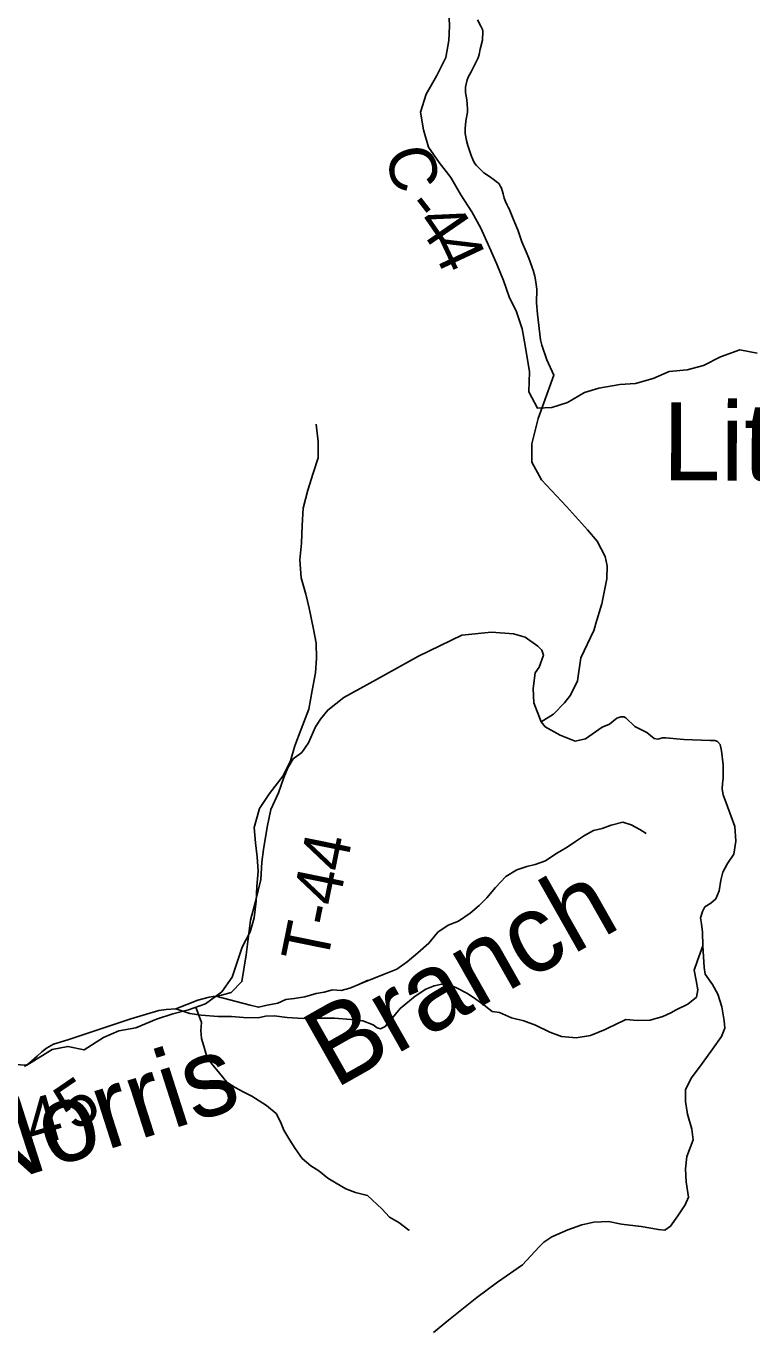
# Model space of a CAD drawing. Extents: x 0 to 34, y 0 to 22.
# Drawn here: x 5.252 to 6.132, y 18.512 to 20.093 of the extents above; entities that cross this region are included whole.
import ezdxf

# ---------------------------------------------------------------- set-up
doc = ezdxf.new("R2010")
doc.units = 0
for name, color, linetype in [('GM_X_County_Road', 7, 'Continuous'), ('GM_X_County_Road_Text', 7, 'Continuous'), ('GM_X_Minor_River', 7, 'Continuous'), ('GM_X_Minor_River_Text', 7, 'Continuous'), ('GM_X_Township_Road', 7, 'Continuous'), ('GM_X_Township_Road_Text', 7, 'Continuous')]:
    doc.layers.add(name, color=color, linetype=linetype)

msp = doc.modelspace()

# ---------------------------------------------------------------- linework, layer by layer
at = {"layer": 'GM_X_County_Road'}
for points in [[(5.8698, 19.7849), (5.8688, 19.7894), (5.8668, 19.7965), (5.8659, 19.7997), (5.8634, 19.8067), (5.8618, 19.8111), (5.8584, 19.8189), (5.8531, 19.8311), (5.8486, 19.8442), (5.842, 19.8611), (5.8378, 19.8711), (5.8368, 19.8733), (5.8355, 19.8754), (5.8335, 19.8799), (5.8318, 19.8841), (5.8304, 19.8895), (5.8284, 19.8961), (5.8272, 19.8984), (5.8263, 19.9005), (5.8249, 19.9021), (5.8221, 19.9042), (5.8186, 19.9072), (5.8129, 19.911), (5.807, 19.9148), (5.8013, 19.9205), (5.7981, 19.9236), (5.7958, 19.9267), (5.7936, 19.9309), (5.7916, 19.9357), (5.7901, 19.9406), (5.7877, 19.948), (5.7861, 19.9541), (5.7843, 19.9626), (5.7843, 19.9686), (5.7852, 19.9774), (5.7873, 19.9885), (5.7871, 19.9921), (5.787, 19.9988), (5.7863, 20.0033), (5.7848, 20.0124), (5.7848, 20.0187), (5.7856, 20.0226), (5.787, 20.0279), (5.7885, 20.032), (5.7916, 20.0374), (5.8004, 20.0543), (5.8015, 20.0584), (5.8028, 20.0651), (5.8056, 20.0761), (5.8057, 20.0868), (5.8053, 20.0889), (5.8048, 20.0905), (5.8033, 20.093), (5.7996, 20.1007)], [(5.9427, 19.3663), (5.9504, 19.3912), (5.9562, 19.4218), (5.9568, 19.4375), (5.9545, 19.449), (5.9445, 19.4675), (5.9329, 19.4813), (5.9076, 19.5097), (5.8769, 19.542), (5.8653, 19.5635), (5.8653, 19.5858), (5.873, 19.6166), (5.8922, 19.6692), (5.8834, 19.6876), (5.8773, 19.7057), (5.876, 19.7119), (5.8723, 19.743), (5.871, 19.7568), (5.8713, 19.7736), (5.8698, 19.7849)], [(5.8768, 19.2482), (5.8917, 19.2573), (5.9049, 19.2713), (5.9124, 19.2804), (5.9206, 19.2978), (5.9248, 19.3259), (5.9405, 19.359), (5.9422, 19.3644), (5.9427, 19.3663)], [(5.9738, 18.8837), (5.9793, 18.8865), (5.9934, 18.8852), (6.0088, 18.8856), (6.0242, 18.8901), (6.0342, 18.8945), (6.0406, 18.8984), (6.0547, 18.9051), (6.0653, 18.9138), (6.0669, 18.9228), (6.0647, 18.934), (6.0624, 18.9465), (6.0663, 18.9584), (6.073, 18.9761)], [(5.9981, 18.6352), (6.0189, 18.6314), (6.0269, 18.6306), (6.0335, 18.6357), (6.0426, 18.648), (6.0513, 18.6617), (6.0555, 18.6707), (6.0527, 18.6893), (6.052, 18.7052), (6.0534, 18.7204), (6.061, 18.7405), (6.0596, 18.7536), (6.0541, 18.7716), (6.052, 18.7868), (6.052, 18.8014), (6.0589, 18.8159), (6.0721, 18.8332), (6.0845, 18.8505), (6.0956, 18.866), (6.0994, 18.8762), (6.0986, 18.8849), (6.0961, 18.902), (6.0911, 18.9173), (6.0845, 18.9289), (6.0758, 18.9418), (6.0745, 18.9497), (6.073, 18.9761)], [(5.2497, 18.8294), (5.2548, 18.833), (5.2651, 18.842), (5.2706, 18.8475), (5.2762, 18.8518), (5.2848, 18.8567), (5.3024, 18.862), (5.3788, 18.8872), (5.4128, 18.8977), (5.4216, 18.8987), (5.4333, 18.8997), (5.4502, 18.894), (5.4641, 18.8919), (5.4849, 18.8902), (5.5008, 18.8902), (5.5155, 18.8892), (5.5331, 18.8885), (5.5423, 18.8906), (5.5525, 18.8909), (5.5685, 18.8889), (5.5879, 18.8879), (5.6039, 18.8882), (5.626, 18.8882), (5.6457, 18.8865), (5.6603, 18.8848), (5.6729, 18.88), (5.6777, 18.8763), (5.6817, 18.8753), (5.6875, 18.878), (5.6943, 18.8861), (5.7055, 18.8998), (5.7239, 18.9151), (5.7368, 18.9236), (5.747, 18.9274), (5.7563, 18.9295), (5.7649, 18.9287), (5.774, 18.9251), (5.7871, 18.9183), (5.7973, 18.9113), (5.8075, 18.9039), (5.8173, 18.8962), (5.8263, 18.8949), (5.8407, 18.8885), (5.8555, 18.8849), (5.8696, 18.8798), (5.8872, 18.8714), (5.9014, 18.866), (5.9193, 18.8644), (5.9366, 18.8673), (5.9543, 18.8743), (5.971, 18.8824), (5.9738, 18.8837)], [(5.7461, 18.5063), (5.7644, 18.5215), (5.7984, 18.549), (5.8237, 18.5677), (5.8541, 18.5888), (5.8741, 18.6105), (5.88, 18.6163), (5.8896, 18.6225), (5.9092, 18.631), (5.9261, 18.6371), (5.9407, 18.6405), (5.9582, 18.6411), (5.9741, 18.6381), (5.9981, 18.6352)]]:
    msp.add_lwpolyline(points, dxfattribs=at)
at = {"layer": 'GM_X_Minor_River'}
for points in [[(6.1389, 19.6958), (6.1177, 19.6997), (6.0942, 19.6914), (6.0737, 19.6808), (6.054, 19.6756), (6.0321, 19.6734), (6.0124, 19.6651), (5.9912, 19.6591), (5.9722, 19.6576), (5.9465, 19.6532), (5.9291, 19.6479), (5.9086, 19.6358), (5.8896, 19.6298), (5.8722, 19.6291), (5.8617, 19.6489), (5.8625, 19.6731), (5.8573, 19.705), (5.8536, 19.7255), (5.8469, 19.746), (5.8378, 19.7642), (5.8311, 19.784), (5.8228, 19.8037), (5.8138, 19.8242), (5.8033, 19.8477), (5.7927, 19.8675), (5.7792, 19.888), (5.7671, 19.9093), (5.7528, 19.9275), (5.74, 19.9458), (5.734, 19.967), (5.7303, 19.9883), (5.7372, 20.0102), (5.7501, 20.033), (5.7608, 20.0549), (5.7646, 20.0754), (5.7654, 20.0928), (5.7647, 20.1126)], [(5.6035, 19.6097), (5.6061, 19.588), (5.606, 19.5686), (5.5999, 19.55), (5.5935, 19.5295), (5.5877, 19.5074), (5.5865, 19.4865), (5.5857, 19.4652), (5.5838, 19.4447), (5.5856, 19.423), (5.5909, 19.4032), (5.595, 19.3861), (5.6003, 19.3606), (5.6036, 19.3435), (5.604, 19.3256), (5.6028, 19.3077), (5.5986, 19.2861), (5.5947, 19.2636), (5.5856, 19.2393), (5.5776, 19.2188), (5.5726, 19.2009), (5.5635, 19.1827), (5.5472, 19.161), (5.535, 19.1427), (5.5285, 19.1199), (5.53, 19.1013), (5.5319, 19.0842), (5.5333, 19.0667), (5.5318, 19.048), (5.531, 19.0302), (5.5283, 19.01), (5.5237, 18.9929), (5.5138, 18.9743), (5.5077, 18.9564), (5.5016, 18.9381), (5.4891, 18.9203), (5.4694, 18.9058), (5.4489, 18.8982), (5.4296, 18.8933), (5.4099, 18.8869), (5.3849, 18.8766), (5.364, 18.8728), (5.3455, 18.8649), (5.322, 18.8497), (5.3023, 18.8539), (5.2834, 18.8501), (5.2527, 18.8311), (5.2292, 18.8323)], [(5.656, 18.9295), (5.6916, 18.9436), (5.7014, 18.9478), (5.7139, 18.9565), (5.7272, 18.9675), (5.7404, 18.9792), (5.7514, 18.9925), (5.7639, 19.0012), (5.7764, 19.0061), (5.7904, 19.0156), (5.8014, 19.0251), (5.8108, 19.0345), (5.8214, 19.047), (5.8339, 19.0603), (5.8472, 19.0683), (5.8593, 19.0724), (5.8695, 19.0747), (5.882, 19.0792), (5.8945, 19.0876), (5.9081, 19.0959), (5.9183, 19.1027), (5.9293, 19.1099), (5.9403, 19.116), (5.9505, 19.1187), (5.9615, 19.1224), (5.9759, 19.1262), (5.9857, 19.1232), (5.9963, 19.1175), (6.0039, 19.1126)], [(5.4819, 18.915), (5.5237, 18.9038), (5.5335, 18.9015), (5.5441, 18.9038), (5.557, 18.9064), (5.5668, 18.9109), (5.5771, 18.912), (5.5899, 18.9142), (5.6036, 18.918), (5.6134, 18.9198), (5.6236, 18.9225), (5.6339, 18.9217), (5.6445, 18.9246), (5.6562, 18.9295), (5.6664, 18.9344)], [(5.4577, 18.9015), (5.4646, 18.8828), (5.4638, 18.8733), (5.4645, 18.8635), (5.4672, 18.854), (5.4705, 18.843), (5.4766, 18.8331), (5.4864, 18.8216), (5.4951, 18.8106), (5.5053, 18.8041), (5.5151, 18.7988), (5.5257, 18.7934), (5.5434, 18.782), (5.5551, 18.7724), (5.5604, 18.7622), (5.5645, 18.7523), (5.5717, 18.7401), (5.5781, 18.7299), (5.5868, 18.7177), (5.597, 18.7089), (5.6068, 18.7028), (5.6178, 18.694), (5.628, 18.6879), (5.6397, 18.6811), (5.6514, 18.6765), (5.6627, 18.6738), (5.6658, 18.673)], [(5.6658, 18.673), (5.6832, 18.6567), (5.6926, 18.6464), (5.704, 18.64), (5.7161, 18.6309), (5.7165, 18.6316)]]:
    msp.add_lwpolyline(points, dxfattribs=at)
at = {"layer": 'GM_X_Township_Road'}
for points in [[(5.6768, 19.2996), (5.728, 19.328), (5.7802, 19.3532), (5.8162, 19.3568), (5.843, 19.3548), (5.8573, 19.351), (5.8727, 19.3399), (5.8775, 19.3352), (5.8793, 19.3292), (5.8744, 19.3143), (5.8694, 19.3077), (5.8669, 19.2887), (5.8678, 19.2713), (5.8768, 19.2482), (5.8815, 19.2421), (5.8999, 19.2317), (5.9178, 19.2247), (5.9305, 19.2276), (5.9506, 19.2415), (5.9594, 19.2454), (5.9686, 19.2524), (5.9732, 19.2542), (5.9769, 19.2543), (5.9795, 19.253), (5.9905, 19.2426), (6.005, 19.235), (6.0139, 19.2277), (6.0181, 19.227), (6.0238, 19.2286), (6.028, 19.2288), (6.0499, 19.2265), (6.0818, 19.2254), (6.0874, 19.2253), (6.0905, 19.2242), (6.0937, 19.2207), (6.0956, 19.2127), (6.0977, 19.1957), (6.0977, 19.1794), (6.0966, 19.1731), (6.0964, 19.1663), (6.0977, 19.1595), (6.1029, 19.1451), (6.1116, 19.1209), (6.1127, 19.103), (6.1104, 19.0874), (6.1029, 19.0759), (6.0972, 19.0655), (6.0949, 19.0557), (6.0926, 19.043), (6.0885, 19.0332), (6.0827, 19.028), (6.0752, 19.0234), (6.0724, 19.0176), (6.0701, 19.0101), (6.0712, 19.0026), (6.0724, 18.9928), (6.073, 18.9761)], [(5.4333, 18.8997), (5.4602, 18.9102), (5.4739, 18.9136), (5.4888, 18.9161), (5.5005, 18.9195), (5.5136, 18.9326), (5.5185, 18.9653), (5.5238, 19.0074), (5.53, 19.03), (5.5366, 19.0565), (5.5376, 19.0776), (5.5398, 19.0929), (5.5443, 19.1203), (5.5487, 19.1417), (5.558, 19.1618), (5.5644, 19.1803), (5.5691, 19.1921), (5.5759, 19.2033), (5.5862, 19.2109), (5.5943, 19.2224), (5.603, 19.2422), (5.6087, 19.2512), (5.6176, 19.2623), (5.6372, 19.2775), (5.6768, 19.2996)]]:
    msp.add_lwpolyline(points, dxfattribs=at)

# ---------------------------------------------------------------- texts
at = {"layer": 'GM_X_County_Road_Text'}
for s, rotation, p in [('C', 284.4291, (5.6866, 19.94)), ('-', 307.9436, (5.7093, 19.8721)), ('4', 304.5806, (5.7232, 19.8544)), ('4', 295.0859, (5.7418, 19.8278)), ('5', 34.3634, (5.3112, 18.7497)), ('4', 16.2034, (5.2599, 18.7315))]:
    msp.add_text(s, height=0.0568, rotation=rotation, dxfattribs=at).set_placement(p)
at = {"layer": 'GM_X_Minor_River_Text'}
for s, height, rotation, p in [('Little', 0.09469, 359.7569, (6.0239, 19.5415)), ('Branch', 0.0947, 29.4973, (5.6264, 18.8018)), ('Norris', 0.0947, 17.7682, (5.1944, 18.6783))]:
    msp.add_text(s, height=height, rotation=rotation, dxfattribs=at).set_placement(p)
at = {"layer": 'GM_X_Township_Road_Text'}
msp.add_text('T-44', height=0.05682, rotation=78.5052, dxfattribs=at).set_placement((5.6164, 18.9524))

doc.saveas('drawing.dxf')
